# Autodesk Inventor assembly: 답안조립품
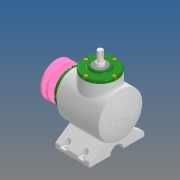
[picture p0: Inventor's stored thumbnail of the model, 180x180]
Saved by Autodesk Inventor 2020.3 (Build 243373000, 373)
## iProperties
Created: 2021-04
Part Number: 답안조립품
Document SubType Name: Assembly
Designer: EZDESIGN
Author: EZDESIGN
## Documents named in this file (17)
- C:\Users\EZDESIGN\Desktop\710407V1007\답안조립품.iam
- C:\Users\EZDESIGN\Desktop\710407V1007\답안본체.ipt
- C:\Users\EZDESIGN\Desktop\710407V1007\서브 베벨기어.ipt
- C:\Users\EZDESIGN\Desktop\710407V1007\서브 축.ipt
- 서브 축.ipt
- C:\Users\EZDESIGN\Desktop\710407V1007\키 4 x 4 x 14.ipt
- C:\Users\EZDESIGN\Desktop\710407V1007\베어링 6203.ipt
- C:\Users\EZDESIGN\Desktop\710407V1007\커버.ipt
- C:\Users\EZDESIGN\Desktop\710407V1007\오일실 17 x 32 x 8.ipt
- C:\Users\EZDESIGN\Desktop\710407V1007\볼트 M4 x 10.ipt
- C:\Users\EZDESIGN\Desktop\710407V1007\메인 베벨기어.ipt
- C:\Users\EZDESIGN\Desktop\710407V1007\키 5 x 5 x 14.ipt
- C:\Users\EZDESIGN\Desktop\710407V1007\메인 축.ipt
- 메인 축.ipt
- C:\Users\EZDESIGN\Desktop\710407V1007\V-벨트풀리.ipt
- C:\Users\EZDESIGN\Desktop\710407V1007\와셔 4 x 16.ipt
- C:\Users\EZDESIGN\Desktop\710407V1007\육각볼트 M4 x 8.ipt
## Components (1 placed, 1 different names)
1. V-벨트풀리:1
